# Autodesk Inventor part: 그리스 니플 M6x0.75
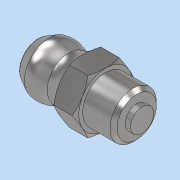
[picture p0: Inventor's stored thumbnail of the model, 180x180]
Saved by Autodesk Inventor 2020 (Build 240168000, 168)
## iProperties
Created: 2024-11
Part Number: 그리스 니플 M6x0.75
Material: 강철, 연강
Description: 윤활 니플, 원추 유형 A
Document SubType Name: Modeling
Designer: 1강의실14
Density: 7.85 g/cm^3
Appearance: 기본값
Author: jhkim
Sending System: Autodesk Inventor 2025
Preprocessor: ST-DEVELOPER v20
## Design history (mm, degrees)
node "그리스 니플 M6x0.751"
node "솔리드1"
body "Solid1"
